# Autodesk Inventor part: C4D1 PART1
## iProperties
Shininess: 64.0
Length Units: 11272
Angle Units: 11279
Time Units: 11290
Mass Units: 11283
Length Display Precision: 3
Angle Display Precision: 2
Compacted: True
Part Number: C4D1 PART1
Document SubType Name: Modeling
Created: 2003-01
Designer: Owner
Density: 0.0
Volumn: 0.0
Area: 0.0
PropertySet Name: Model Information
Control State: 0
Master: False
Checked Out: False
Author: Owner
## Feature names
1. ExtrusionBlind1
2. ExtrusionBlind2
3. ExtrusionBlind3
4. ExtrusionBlind4
5. ExtrusionThru1
6. Hole1
